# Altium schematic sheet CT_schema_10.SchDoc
size 281 x 153 mm
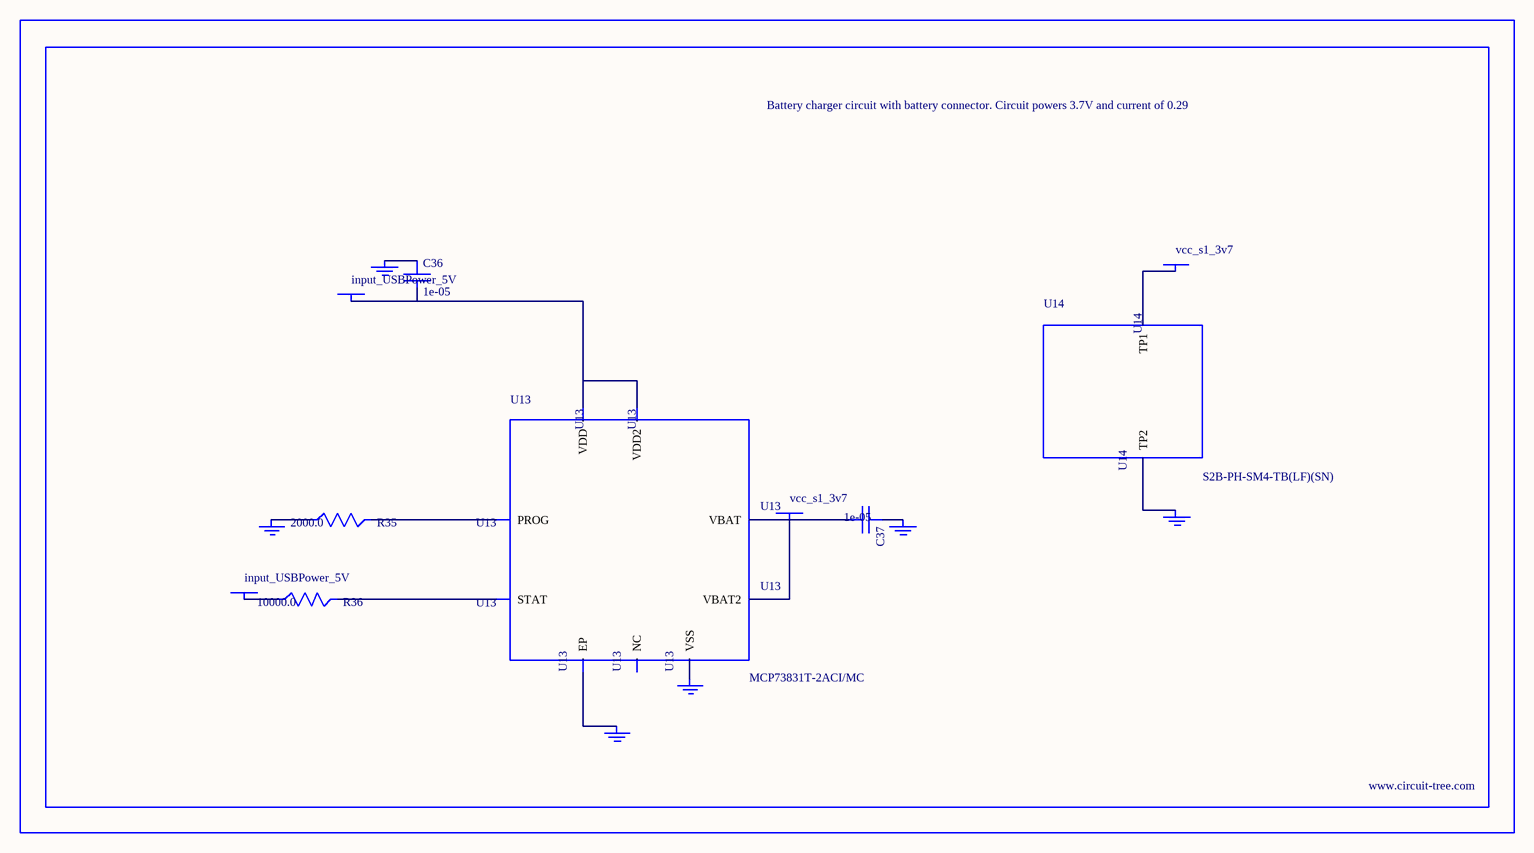
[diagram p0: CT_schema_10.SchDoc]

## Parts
BORDER9  (no value)
C36  1e-05  [C1206]
C37  1e-05  [C1206]
GND_INSTANCE_9_0  (no value)
GND_INSTANCE_9_1  (no value)
GND_INSTANCE_9_2  (no value)
GND_INSTANCE_9_3  (no value)
GND_INSTANCE_9_4  (no value)
GND_INSTANCE_9_5  (no value)
POWER_INSTANCE_9_0  input_USBPower_5V
POWER_INSTANCE_9_1  input_USBPower_5V
POWER_INSTANCE_9_2  vcc_s1_3v7
POWER_INSTANCE_9_3  vcc_s1_3v7
R35  2000.0  [R0603]
R36  10000.0  [R0603]
U13  MCP73831T-2ACI/MC  [DFN8_2X3MC]
U14  S2B-PH-SM4-TB(LF)(SN)  [JST-2-SMD]

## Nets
NetC36_1: C36.1 GND_INSTANCE_9_0.0(GND)
NetC36_2: C36.2 POWER_INSTANCE_9_0.0(PWR) U13.1(VDD) U13.2(VDD2)
NetC37_1: C37.1 GND_INSTANCE_9_1.0(GND)
NetC37_2: C37.2 POWER_INSTANCE_9_2.0(PWR) U13.3(VBAT) U13.4(VBAT2)
NetGND_INSTANCE_9_2_0: GND_INSTANCE_9_2.0(GND) R35.1
NetGND_INSTANCE_9_3_0: GND_INSTANCE_9_3.0(GND) U13.9(EP)
NetGND_INSTANCE_9_4_0: GND_INSTANCE_9_4.0(GND) U13.6(VSS)
NetGND_INSTANCE_9_5_0: GND_INSTANCE_9_5.0(GND) U14.2(TP2)
NetPOWER_INSTANCE_9_1_0: POWER_INSTANCE_9_1.0(PWR) R36.1
NetPOWER_INSTANCE_9_3_0: POWER_INSTANCE_9_3.0(PWR) U14.1(TP1)
NetR35_2: R35.2 U13.8(PROG)
NetR36_2: R36.2 U13.5(STAT)

Not connected (* = marked no-connect by the designer): U13 7(NC)

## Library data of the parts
BORDER9 = BORDER_PAGE9
C36 C37 = C1206C106K3RACTU
GND_INSTANCE_9_0-GND_INSTANCE_9_5 = GND
POWER_INSTANCE_9_0-POWER_INSTANCE_9_3 = PWR
R35 = RC0603JR-072KL
R36 = RC0603JR-0710KL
